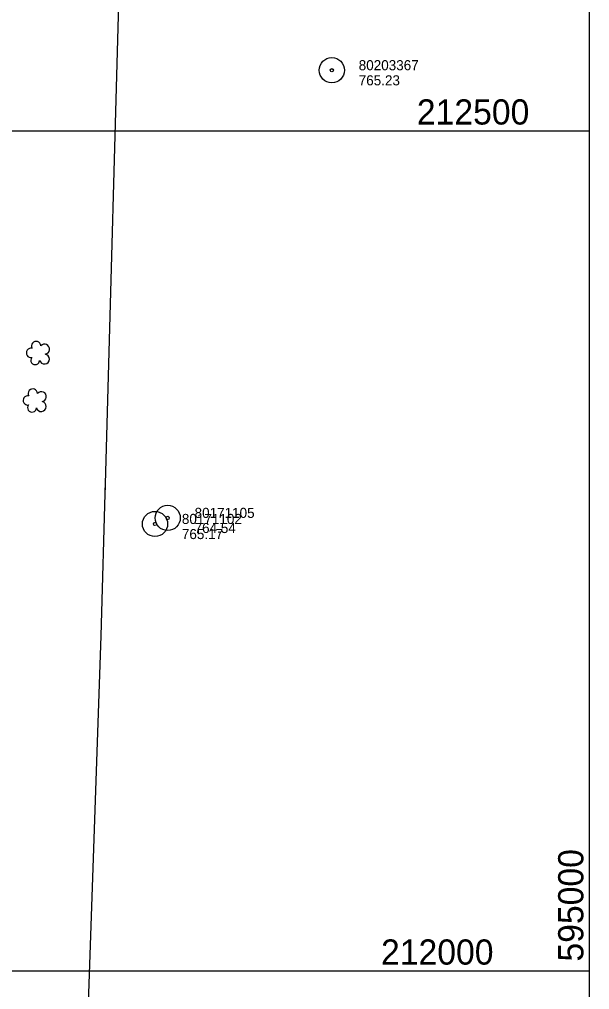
# Model space of a CAD drawing. Extents: x 591954 to 597000, y 198576 to 213500.
# Drawn here: x 594661 to 595000, y 211989 to 212566 of the extents above; entities that cross this region are included whole.
import ezdxf

# ---------------------------------------------------------------- set-up
doc = ezdxf.new("R2010")
doc.units = 0
for name, color, linetype in [('Level 10', 7, 'Continuous'), ('Level 18', 7, 'Continuous'), ('Level 4', 7, 'Continuous'), ('Level 6', 7, 'Continuous')]:
    doc.layers.add(name, color=color, linetype=linetype)

msp = doc.modelspace()

# ---------------------------------------------------------------- linework, layer by layer
at = {"layer": 'Level 10'}
for p, q in [((595000, 212000), (595000, 213500)), ((593000, 212500), (595000, 212500)), ((593000, 212500), (595000, 212500)), ((595000, 211000), (595000, 212500)), ((593000, 212000), (595000, 212000)), ((593000, 212000), (595000, 212000))]:
    msp.add_line(p, q, dxfattribs=at)
at = {"layer": 'Level 18'}
for centre, radius, start, end in [((594670.66, 212371.92), 2.78, 1.39455, 209.16754), ((594675.7, 212370.06), 2.97, 278.42366, 139.65754), ((594667.66, 212367.85), 2.78, 78.07156, 279.08261), ((594675.59, 212364.21), 2.97, 196.07448, 79.04774), ((594670.12, 212363.45), 2.61, 140.77971, 358.71232), ((594668.73, 212343.65), 2.78, 1.39455, 209.16754), ((594673.77, 212341.79), 2.97, 278.42366, 139.65754), ((594665.73, 212339.58), 2.78, 78.07156, 279.08261), ((594673.66, 212335.94), 2.97, 196.07448, 79.04774), ((594668.19, 212335.18), 2.61, 140.77971, 358.71232)]:
    msp.add_arc(centre, radius, start, end, dxfattribs=at)
at = {"layer": 'Level 4'}
for points in [[(594730.22, 212954.9), (594711.46, 212282.55)], [(594711.7, 212291.04), (594709.14, 212199.36)], [(594709.14, 212199.36), (594680.87, 211376.95)]]:
    msp.add_lwpolyline(points, dxfattribs=at)
at = {"layer": 'Level 6'}
for centre, radius in [((594846.62, 212536.07), 7.5), ((594846.62, 212536.07), 0.96), ((594748.97, 212269.62), 7.5), ((594748.97, 212269.62), 7.5), ((594741.4, 212266.01), 7.5), ((594741.4, 212266.01), 7.5), ((594748.97, 212269.62), 0.96), ((594748.97, 212269.62), 0.96), ((594741.4, 212266.01), 0.96), ((594741.4, 212266.01), 0.96)]:
    msp.add_circle(centre, radius, dxfattribs=at)

# ---------------------------------------------------------------- texts
at = {"layer": 'Level 10'}
for s, p in [(' 212500 ', (594891.64, 212503.75)), (' 212000 ', (594870.33, 212003.75))]:
    msp.add_text(s, height=15, dxfattribs=at).set_placement(p)
msp.add_text(' 595000 ', height=15, rotation=90, dxfattribs=at).set_placement((594996.29, 212000))
at = {"layer": 'Level 6'}
for s, p in [('80203367', (594862.62, 212536.07)), ('765.23', (594862.62, 212527.07)), ('80171105', (594764.97, 212269.62)), ('80171105', (594764.97, 212269.62)), ('80171102', (594757.4, 212266.01)), ('80171102', (594757.4, 212266.01)), ('765.17', (594757.4, 212257.01)), ('765.17', (594757.4, 212257.01)), ('764.54', (594764.97, 212260.62)), ('764.54', (594764.97, 212260.62))]:
    msp.add_text(s, height=6, dxfattribs=at).set_placement(p)

doc.saveas('drawing.dxf')
